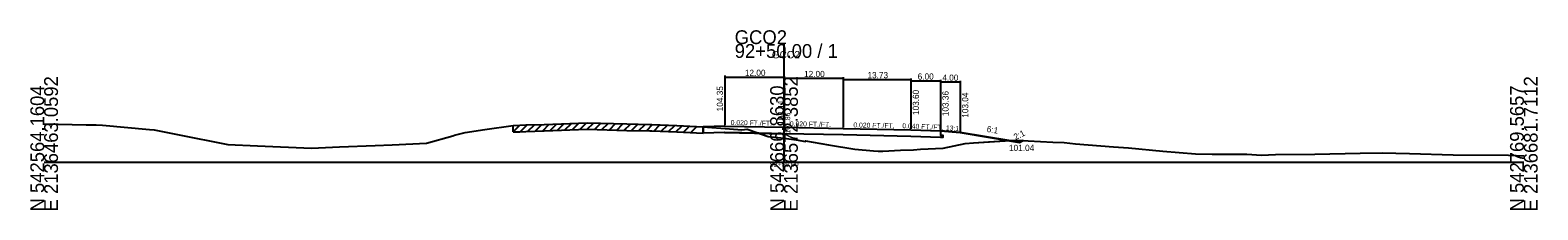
# Model space of a CAD drawing. Extents: x -14327 to 8886, y -10 to 39048.
# Drawn here: x 3997.2 to 4302.8, y 4990.3 to 5026.9 of the extents above; entities that cross this region are included whole.
import ezdxf

# ---------------------------------------------------------------- set-up
doc = ezdxf.new("R2010")
doc.units = 0
for name, color, linetype in [('Level 5', 7, 'Continuous'), ('Level 53', 7, 'Continuous'), ('Level 54', 7, 'Continuous'), ('Level 55', 7, 'Continuous'), ('Level 7', 7, 'Continuous'), ('RD_GPK_XS_Cell', 7, 'Continuous'), ('RD_XS_EwShp', 7, 'Continuous'), ('RD_XS_ExGround', 7, 'Continuous'), ('RD_XS_ExPaveRet', 7, 'Continuous'), ('RD_XS_Pave', 7, 'Continuous'), ('RD_XS_TX_Baseline', 7, 'Continuous'), ('RD_XS_TX_Elev_EX', 7, 'Continuous'), ('RD_XS_TX_Elev_PR', 7, 'Continuous'), ('RD_XS_TX_Station', 7, 'Continuous')]:
    doc.layers.add(name, color=color, linetype=linetype)

msp = doc.modelspace()

# ---------------------------------------------------------------- linework, layer by layer
at = {"layer": 'Level 5'}
for p, q in [((4133.62, 5007.22), (4133.62, 5005.89)), ((4137.95, 5006.02), (4133.62, 5005.89)), ((4137.95, 5006.02), (4150, 5005.78)), ((4150, 5005.78), (4138, 5006.02)), ((4162, 5005.54), (4150, 5005.78)), ((4175.73, 5005.26), (4162, 5005.54)), ((4181.73, 5005.02), (4175.73, 5005.26)), ((4181.73, 5006.36), (4181.73, 5005.52)), ((4181.73, 5005.52), (4182.23, 5005.5)), ((4182.23, 5005), (4181.73, 5005.02)), ((4182.23, 5005.5), (4182.23, 5005))]:
    msp.add_line(p, q, dxfattribs=at)
at = {"layer": 'Level 54'}
for p, q in [((4138, 5017.62), (4138, 5007.55)), ((4138, 5017.5), (4138, 5007.55)), ((4138, 5017.3), (4150, 5017.3)), ((4150, 5017.5), (4150, 5007.31)), ((4150, 5017.26), (4150, 5007.31)), ((4150, 5017.06), (4162, 5017.06)), ((4162, 5017.26), (4162, 5007.07)), ((4162, 5017.02), (4162, 5007.07)), ((4162, 5016.82), (4175.73, 5016.82)), ((4175.73, 5017.02), (4175.73, 5006.8)), ((4175.73, 5016.75), (4175.73, 5006.8)), ((4175.73, 5016.55), (4181.73, 5016.55)), ((4181.73, 5016.75), (4181.73, 5006.56)), ((4181.73, 5016.51), (4181.73, 5006.56)), ((4181.73, 5016.31), (4185.73, 5016.31)), ((4185.73, 5016.51), (4185.73, 5006.24))]:
    msp.add_line(p, q, dxfattribs=at)
at = {"layer": 'Level 7'}
for p, q in [((4181.73, 5006.36), (4185.73, 5006.04)), ((4185.73, 5006.04), (4197.74, 5004.04)), ((4197.74, 5004.04), (4198.49, 5004.41))]:
    msp.add_line(p, q, dxfattribs=at)
at = {"layer": 'RD_GPK_XS_Cell'}
for p, q in [((4150, 5000), (4150, 5024.01)), ((4000, 5000), (4150, 5000)), ((4150, 5000), (4300, 5000))]:
    msp.add_line(p, q, dxfattribs=at)
at = {"layer": 'RD_XS_EwShp'}
for points in [[(4137.95, 5006.02), (4133.62, 5005.89), (4133.62, 5007.22), (4138.93, 5006.8), (4141.45, 5006.56), (4142.52, 5006.7), (4144.93, 5005.88), (4138, 5006.02)], [(4181.73, 5005.02), (4175.73, 5005.26), (4162, 5005.54), (4150, 5005.78), (4144.93, 5005.88), (4146.79, 5005.24), (4150, 5004.86), (4152.47, 5004.57), (4154.35, 5004.22), (4154.38, 5004.38), (4158.99, 5003.56), (4164.39, 5002.65), (4168.16, 5002.33), (4169.08, 5002.25), (4170.06, 5002.26), (4173.62, 5002.42), (4176.28, 5002.5), (4177.69, 5002.65), (4182.28, 5002.87), (4186.76, 5003.8), (4188.42, 5003.92), (4195.58, 5004.39), (4185.73, 5006.04), (4181.73, 5006.36), (4181.73, 5005.52), (4182.23, 5005.5), (4182.23, 5005)], [(4195.58, 5004.39), (4197, 5004.49), (4198.49, 5004.41), (4197.74, 5004.04)]]:
    msp.add_lwpolyline(points, close=True, dxfattribs=at)
at = {"layer": 'RD_XS_ExGround'}
for p, q in [((4000, 5007.79), (4008.52, 5007.62)), ((4008.52, 5007.62), (4010.56, 5007.57)), ((4010.56, 5007.57), (4011.81, 5007.52)), ((4011.81, 5007.52), (4021.33, 5006.67)), ((4089.36, 5006.63), (4095.07, 5007.47)), ((4095.07, 5007.47), (4096.45, 5007.51)), ((4096.45, 5007.51), (4097.66, 5007.57)), ((4097.66, 5007.57), (4101.4, 5007.7)), ((4101.4, 5007.7), (4110.11, 5008)), ((4110.11, 5008), (4118.16, 5007.78)), ((4118.16, 5007.78), (4122.81, 5007.65)), ((4122.81, 5007.65), (4123.21, 5007.65)), ((4123.21, 5007.65), (4128.26, 5007.46)), ((4128.26, 5007.46), (4133.62, 5007.22)), ((4133.62, 5007.22), (4138.93, 5006.8)), ((4021.33, 5006.67), (4022.33, 5006.57)), ((4022.33, 5006.57), (4023.67, 5006.34)), ((4023.67, 5006.34), (4025, 5006.03)), ((4025, 5006.03), (4027.04, 5005.64)), ((4027.04, 5005.64), (4037.22, 5003.59)), ((4077.54, 5003.87), (4082.86, 5005.37)), ((4082.86, 5005.37), (4083.22, 5005.48)), ((4083.22, 5005.48), (4085.35, 5006.03)), ((4085.35, 5006.03), (4089.36, 5006.63)), ((4138.93, 5006.8), (4141.45, 5006.56)), ((4141.45, 5006.56), (4142.52, 5006.7)), ((4142.52, 5006.7), (4146.79, 5005.24)), ((4146.79, 5005.24), (4150, 5004.86)), ((4150, 5004.86), (4152.47, 5004.57)), ((4152.47, 5004.57), (4154.35, 5004.22)), ((4154.35, 5004.22), (4154.38, 5004.38)), ((4154.38, 5004.38), (4158.99, 5003.56)), ((4188.42, 5003.92), (4197, 5004.49)), ((4197, 5004.49), (4204.48, 5004.11)), ((4204.48, 5004.11), (4206.78, 5004)), ((4037.22, 5003.59), (4043.26, 5003.34)), ((4043.26, 5003.34), (4054.23, 5002.85)), ((4054.23, 5002.85), (4059.91, 5003.11)), ((4059.91, 5003.11), (4067.09, 5003.38)), ((4067.09, 5003.38), (4070.55, 5003.53)), ((4070.55, 5003.53), (4077.54, 5003.87)), ((4158.99, 5003.56), (4164.39, 5002.65)), ((4164.39, 5002.65), (4168.16, 5002.33)), ((4168.16, 5002.33), (4169.08, 5002.25)), ((4169.08, 5002.25), (4170.06, 5002.26)), ((4170.06, 5002.26), (4173.62, 5002.42)), ((4173.62, 5002.42), (4176.28, 5002.5)), ((4176.28, 5002.5), (4177.69, 5002.65)), ((4177.69, 5002.65), (4182.28, 5002.87)), ((4182.28, 5002.87), (4186.76, 5003.8)), ((4186.76, 5003.8), (4188.42, 5003.92)), ((4206.78, 5004), (4209.08, 5003.76)), ((4209.08, 5003.76), (4216.79, 5003.16)), ((4216.79, 5003.16), (4219.82, 5002.9)), ((4219.82, 5002.9), (4226.8, 5002.23)), ((4226.8, 5002.23), (4233.45, 5001.72)), ((4233.45, 5001.72), (4236.81, 5001.64)), ((4236.81, 5001.64), (4243.86, 5001.64)), ((4243.86, 5001.64), (4246.82, 5001.44)), ((4246.82, 5001.44), (4249.68, 5001.55)), ((4249.68, 5001.55), (4257.63, 5001.65)), ((4257.63, 5001.65), (4266.83, 5001.81)), ((4266.83, 5001.81), (4271.3, 5001.94)), ((4271.3, 5001.94), (4276.84, 5001.77)), ((4276.84, 5001.77), (4285.65, 5001.48)), ((4285.65, 5001.48), (4296.86, 5001.41)), ((4296.86, 5001.41), (4300, 5001.27))]:
    msp.add_line(p, q, dxfattribs=at)
at = {"layer": 'RD_XS_ExPaveRet'}
for p, q in [((4095.07, 5006.17), (4096.42, 5007.51)), ((4095.07, 5006.17), (4095.07, 5007.47)), ((4096.57, 5006.22), (4097.93, 5007.58)), ((4098.07, 5006.28), (4099.42, 5007.63)), ((4099.57, 5006.34), (4100.92, 5007.68)), ((4101.07, 5006.39), (4102.42, 5007.73)), ((4102.57, 5006.44), (4103.92, 5007.79)), ((4104.08, 5006.49), (4105.43, 5007.84)), ((4105.58, 5006.55), (4106.93, 5007.89)), ((4107.08, 5006.6), (4108.43, 5007.95)), ((4108.58, 5006.65), (4109.93, 5008)), ((4110.08, 5006.7), (4111.35, 5007.97)), ((4111.58, 5006.66), (4112.85, 5007.93)), ((4113.09, 5006.62), (4114.35, 5007.89)), ((4114.59, 5006.58), (4115.85, 5007.85)), ((4116.09, 5006.54), (4117.35, 5007.81)), ((4117.59, 5006.5), (4118.86, 5007.76)), ((4119.09, 5006.46), (4120.36, 5007.72)), ((4120.59, 5006.42), (4121.86, 5007.68)), ((4122.09, 5006.37), (4123.36, 5007.64)), ((4123.6, 5006.33), (4124.85, 5007.59)), ((4125.1, 5006.28), (4126.35, 5007.53)), ((4126.6, 5006.22), (4127.85, 5007.48)), ((4128.1, 5006.17), (4129.35, 5007.41)), ((4129.6, 5006.1), (4130.85, 5007.34)), ((4131.1, 5006.03), (4132.35, 5007.27)), ((4133.62, 5007.22), (4133.62, 5005.92)), ((4095.07, 5006.17), (4096.45, 5006.21)), ((4096.45, 5006.21), (4097.66, 5006.27)), ((4097.66, 5006.27), (4101.4, 5006.4)), ((4101.4, 5006.4), (4110.11, 5006.7)), ((4110.11, 5006.7), (4118.16, 5006.48)), ((4118.16, 5006.48), (4122.81, 5006.35)), ((4122.81, 5006.35), (4123.21, 5006.35)), ((4123.21, 5006.35), (4128.26, 5006.16)), ((4128.26, 5006.16), (4133.62, 5005.92))]:
    msp.add_line(p, q, dxfattribs=at)
at = {"layer": 'RD_XS_Pave'}
for p, q in [((4138, 5007.35), (4133.62, 5007.22)), ((4138, 5007.35), (4150, 5007.11)), ((4150, 5007.11), (4162, 5006.87)), ((4162, 5006.87), (4175.73, 5006.6)), ((4175.73, 5006.6), (4181.73, 5006.36))]:
    msp.add_line(p, q, dxfattribs=at)

# ---------------------------------------------------------------- texts
at = {"layer": 'Level 53'}
for s, rotation, p in [('104.35', 90, (4137.63, 5010.35)), ('103.60', 90, (4177.35, 5009.6)), ('103.36', 90, (4183.36, 5009.36)), ('103.04', 90, (4187.36, 5009.04)), ('6:1', 350.541, (4191.03, 5006.17))]:
    msp.add_text(s, height=1.25, rotation=rotation, dxfattribs=at).set_placement(p)
msp.add_text('101.04', height=1.25, dxfattribs=at).set_placement((4195.62, 5002.29))
at = {"layer": 'Level 54'}
for s, p in [('12.00', (4142.07, 5017.55)), ('12.00', (4154.07, 5017.31)), ('13.73', (4166.92, 5017.07)), ('6.00', (4177.1, 5016.8)), ('4.00', (4182.1, 5016.56))]:
    msp.add_text(s, height=1.25, dxfattribs=at).set_placement(p)
at = {"layer": 'Level 55'}
for s, height, rotation, p in [('0.020 FT./FT.', 1, 358.8542, (4139.18, 5007.58)), ('0.020 FT./FT.', 1, 358.8542, (4151.18, 5007.34)), ('0.020 FT./FT.', 1, 358.8542, (4164.05, 5007.08)), ('0.040 FT./FT.', 1, 357.7094, (4173.97, 5006.92)), ('13:1', 1, 355.4277, (4182.8, 5006.52)), ('2:1', 1.25, 26.5569, (4196.94, 5004.47))]:
    msp.add_text(s, height=height, rotation=rotation, dxfattribs=at).set_placement(p)
at = {"layer": 'RD_GPK_XS_Cell'}
for s, p in [('GCO2', (4140, 5024.01)), ('92+50.00 / 1', (4140, 5021.21))]:
    msp.add_text(s, height=2.8, dxfattribs=at).set_placement(p)
for s, p in [('E 2136463.0592', (4002.8, 4990)), ('E 2136572.3852', (4152.8, 4990)), ('E 2136681.7112', (4302.8, 4990)), ('N 542564.1604', (4000, 4990)), ('N 542666.8630', (4150, 4990)), ('N 542769.5657', (4300, 4990))]:
    msp.add_text(s, height=2.8, rotation=90, dxfattribs=at).set_placement(p)
at = {"layer": 'RD_XS_TX_Baseline'}
msp.add_text('GCO2', height=1.5, dxfattribs=at).set_placement((4147.55, 5021.11))
at = {"layer": 'RD_XS_TX_Elev_EX'}
msp.add_text('101.86', height=1, rotation=90, dxfattribs=at).set_placement((4151.25, 5005.86))
at = {"layer": 'RD_XS_TX_Elev_PR'}
msp.add_text(' 104.11', height=1.25, rotation=90, dxfattribs=at).set_placement((4150, 5007.11))
at = {"layer": 'RD_XS_TX_Station'}
msp.add_text('92+50.00', height=1, dxfattribs=at).set_placement((4147.16, 4999.11))

doc.saveas('drawing.dxf')
